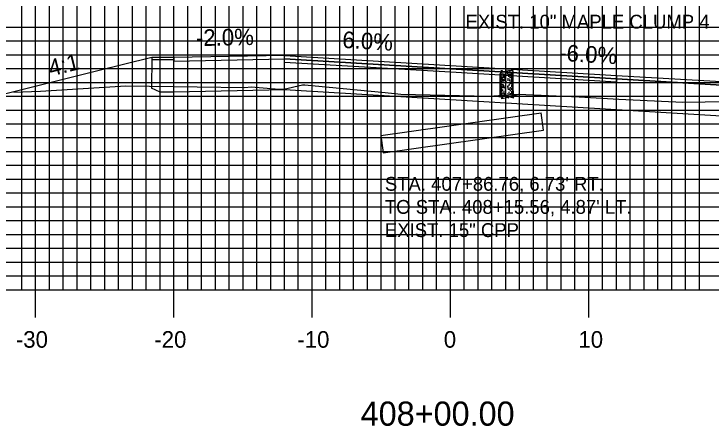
# Model space of a CAD drawing. Extents: x 852529 to 852872, y 364785 to 365005.
# Drawn here: x 852663.2 to 852713.6, y 364896.4 to 364926.2 of the extents above; entities that cross this region are included whole.
import ezdxf

# ---------------------------------------------------------------- set-up
doc = ezdxf.new("R2010")
doc.units = 0
for name, color, linetype in [('ANNOTATION', 7, 'Continuous'), ('D_Drainage_Culvert', 7, 'Continuous'), ('D_Roadway_Centerline', 7, 'Continuous'), ('D_Roadway_Edge_Shoulder', 7, 'Continuous'), ('D_Roadway_Edge_TW', 7, 'Continuous'), ('D_Roadway_Pavement', 7, 'Continuous'), ('D_Roadway_SubGrade', 7, 'Continuous'), ('D_Text_Monospaced', 7, 'Continuous'), ('H_V ANNOTATION', 7, 'Continuous'), ('MAJOR', 7, 'Continuous'), ('MINOR', 7, 'Continuous'), ('S_Roadway_Centerline', 7, 'Continuous'), ('S_Trees_Decid_NonPay', 7, 'Continuous')]:
    doc.layers.add(name, color=color, linetype=linetype)

msp = doc.modelspace()

# ---------------------------------------------------------------- linework, layer by layer
at = {"layer": 'ANNOTATION'}
for points in [[(852673.131, 364923.038), (852669.131, 364922.038), (852656.377, 364918.85)], [(852674.731, 364923.022), (852673.131, 364923.038), (852673.108, 364920.805)], [(852674.729, 364922.856), (852673.129, 364922.872)], [(852674.731, 364920.522), (852673.731, 364920.522), (852673.108, 364920.805)]]:
    msp.add_lwpolyline(points, dxfattribs=at)
at = {"layer": 'D_Drainage_Culvert'}
msp.add_line((852689.688, 364917.382), (852701.285, 364919.019), dxfattribs=at)
msp.add_lwpolyline([(852689.688, 364917.382), (852689.863, 364916.144), (852701.46, 364917.781), (852701.285, 364919.019)], dxfattribs=at)
at = {"layer": 'D_Roadway_Edge_Shoulder'}
for points in [[(852682.731, 364923.182), (852674.731, 364923.022), (852674.731, 364922.772), (852682.731, 364922.932)], [(852706.731, 364921.742), (852714.731, 364921.262), (852714.731, 364921.012), (852706.731, 364921.492)]]:
    msp.add_lwpolyline(points, close=True, dxfattribs=at)
at = {"layer": 'D_Roadway_Edge_TW'}
msp.add_lwpolyline([(852682.731, 364922.932), (852682.731, 364923.182), (852694.731, 364922.462), (852706.731, 364921.742), (852706.731, 364921.492), (852694.731, 364922.212)], close=True, dxfattribs=at)
at = {"layer": 'D_Roadway_Pavement'}
msp.add_lwpolyline([(852682.731, 364922.682), (852682.731, 364922.932), (852694.731, 364922.212), (852706.731, 364921.492), (852706.731, 364921.242), (852694.731, 364921.962)], close=True, dxfattribs=at)
at = {"layer": 'D_Roadway_SubGrade'}
msp.add_lwpolyline([(852682.731, 364920.682), (852674.731, 364920.522), (852674.731, 364922.772), (852674.731, 364923.022), (852674.731, 364922.772), (852682.731, 364922.932), (852694.731, 364922.212), (852706.731, 364921.492), (852714.731, 364921.012), (852714.731, 364921.262), (852727.889, 364917.973), (852706.731, 364919.242), (852694.731, 364919.962)], close=True, dxfattribs=at)
at = {"layer": 'MAJOR'}
for p, q in [((852664.731, 364906.233), (852664.731, 364936.233)), ((852674.731, 364906.233), (852674.731, 364936.233)), ((852684.731, 364906.233), (852684.731, 364936.233)), ((852694.731, 364906.233), (852694.731, 364936.233)), ((852704.731, 364906.233), (852704.731, 364936.233)), ((852554.731, 364921.233), (852834.731, 364921.233)), ((852554.731, 364916.233), (852834.731, 364916.233)), ((852554.731, 364911.233), (852834.731, 364911.233)), ((852554.731, 364906.233), (852834.731, 364906.233)), ((852554.731, 364906.233), (852834.731, 364906.233)), ((852664.731, 364904.229), (852664.731, 364906.233)), ((852674.731, 364904.229), (852674.731, 364906.233)), ((852684.731, 364904.229), (852684.731, 364906.233)), ((852694.731, 364904.229), (852694.731, 364906.233)), ((852704.731, 364904.229), (852704.731, 364906.233))]:
    msp.add_line(p, q, dxfattribs=at)
at = {"layer": 'MINOR'}
for p, q in [((852663.731, 364906.233), (852663.731, 364936.233)), ((852665.731, 364906.233), (852665.731, 364936.233)), ((852666.731, 364906.233), (852666.731, 364936.233)), ((852667.731, 364906.233), (852667.731, 364936.233)), ((852668.731, 364906.233), (852668.731, 364936.233)), ((852669.731, 364906.233), (852669.731, 364936.233)), ((852670.731, 364906.233), (852670.731, 364936.233)), ((852671.731, 364906.233), (852671.731, 364936.233)), ((852672.731, 364906.233), (852672.731, 364936.233)), ((852673.731, 364906.233), (852673.731, 364936.233)), ((852675.731, 364906.233), (852675.731, 364936.233)), ((852676.731, 364906.233), (852676.731, 364936.233)), ((852677.731, 364906.233), (852677.731, 364936.233)), ((852678.731, 364906.233), (852678.731, 364936.233)), ((852679.731, 364906.233), (852679.731, 364936.233)), ((852680.731, 364906.233), (852680.731, 364936.233)), ((852681.731, 364906.233), (852681.731, 364936.233)), ((852682.731, 364906.233), (852682.731, 364936.233)), ((852683.731, 364906.233), (852683.731, 364936.233)), ((852685.731, 364906.233), (852685.731, 364936.233)), ((852686.731, 364906.233), (852686.731, 364936.233)), ((852687.731, 364906.233), (852687.731, 364936.233)), ((852688.731, 364906.233), (852688.731, 364936.233)), ((852689.731, 364906.233), (852689.731, 364936.233)), ((852690.731, 364906.233), (852690.731, 364936.233)), ((852691.731, 364906.233), (852691.731, 364936.233)), ((852692.731, 364906.233), (852692.731, 364936.233)), ((852693.731, 364906.233), (852693.731, 364936.233)), ((852695.731, 364906.233), (852695.731, 364936.233)), ((852696.731, 364906.233), (852696.731, 364936.233)), ((852697.731, 364906.233), (852697.731, 364936.233)), ((852698.731, 364906.233), (852698.731, 364936.233)), ((852699.731, 364906.233), (852699.731, 364936.233)), ((852700.731, 364906.233), (852700.731, 364936.233)), ((852701.731, 364906.233), (852701.731, 364936.233)), ((852702.731, 364906.233), (852702.731, 364936.233)), ((852703.731, 364906.233), (852703.731, 364936.233)), ((852705.731, 364906.233), (852705.731, 364936.233)), ((852706.731, 364906.233), (852706.731, 364936.233)), ((852707.731, 364906.233), (852707.731, 364936.233)), ((852708.731, 364906.233), (852708.731, 364936.233)), ((852709.731, 364906.233), (852709.731, 364936.233)), ((852710.731, 364906.233), (852710.731, 364936.233)), ((852711.731, 364906.233), (852711.731, 364936.233)), ((852712.731, 364906.233), (852712.731, 364936.233)), ((852554.731, 364925.233), (852834.731, 364925.233)), ((852554.731, 364924.233), (852834.731, 364924.233)), ((852554.731, 364923.233), (852834.731, 364923.233)), ((852554.731, 364922.233), (852834.731, 364922.233)), ((852554.731, 364920.233), (852834.731, 364920.233)), ((852554.731, 364919.233), (852834.731, 364919.233)), ((852554.731, 364918.233), (852834.731, 364918.233)), ((852554.731, 364917.233), (852834.731, 364917.233)), ((852554.731, 364915.233), (852834.731, 364915.233)), ((852554.731, 364914.233), (852834.731, 364914.233)), ((852554.731, 364913.233), (852834.731, 364913.233)), ((852554.731, 364912.233), (852834.731, 364912.233)), ((852554.731, 364910.233), (852834.731, 364910.233)), ((852554.731, 364909.233), (852834.731, 364909.233)), ((852554.731, 364908.233), (852834.731, 364908.233)), ((852554.731, 364907.233), (852834.731, 364907.233))]:
    msp.add_line(p, q, dxfattribs=at)
at = {"layer": 'S_Roadway_Centerline'}
msp.add_lwpolyline([(852663.161, 364920.514), (852665.079, 364920.607), (852671.255, 364920.977), (852676.427, 364920.918), (852679.854, 364920.868), (852680.309, 364920.901), (852682.352, 364920.749), (852682.626, 364920.735), (852682.68, 364920.729), (852682.692, 364920.734), (852684.028, 364921.061), (852684.206, 364921.051), (852690.005, 364920.496), (852691.134, 364920.38), (852697.501, 364920.227), (852699.627, 364920.388), (852704.045, 364920.178), (852706.906, 364920.03), (852711.535, 364919.803), (852719.634, 364919.912)], dxfattribs=at)
at = {"layer": 'S_Trees_Decid_NonPay'}
for p, q in [((852698.351, 364921.742), (852698.351, 364921.66)), ((852698.378, 364921.812), (852698.378, 364921.595)), ((852698.421, 364921.807), (852698.421, 364921.755)), ((852698.421, 364921.652), (852698.421, 364921.57)), ((852698.578, 364921.818), (852698.578, 364921.739)), ((852698.578, 364921.652), (852698.578, 364921.568)), ((852698.876, 364921.87), (852698.876, 364921.763)), ((852699.023, 364921.916), (852699.023, 364921.768)), ((852699.023, 364921.72), (852699.023, 364921.551)), ((852699.141, 364921.899), (852699.141, 364921.598)), ((852699.21, 364921.986), (852699.21, 364921.891)), ((852699.21, 364921.665), (852699.21, 364921.582)), ((852698.351, 364921.591), (852698.351, 364921.461)), ((852698.351, 364921.438), (852698.351, 364921.257)), ((852698.351, 364921.209), (852698.351, 364920.963)), ((852698.378, 364921.526), (852698.378, 364921.374)), ((852698.378, 364921.269), (852698.378, 364921.191)), ((852698.378, 364921.164), (852698.378, 364921.057)), ((852698.421, 364921.535), (852698.421, 364921.461)), ((852698.421, 364921.434), (852698.421, 364921.374)), ((852698.421, 364921.321), (852698.421, 364921.14)), ((852698.492, 364921.634), (852698.492, 364921.547)), ((852698.492, 364921.477), (852698.492, 364921.356)), ((852698.492, 364921.28), (852698.492, 364921.166)), ((852698.578, 364921.457), (852698.578, 364921.356)), ((852698.578, 364921.271), (852698.578, 364921.195)), ((852698.696, 364921.634), (852698.696, 364921.434)), ((852698.876, 364921.535), (852698.876, 364921.448)), ((852698.876, 364921.413), (852698.876, 364921.343)), ((852699.023, 364921.245), (852699.023, 364921.096)), ((852699.141, 364921.57), (852699.141, 364921.438)), ((852699.141, 364921.404), (852699.141, 364921.123)), ((852699.21, 364921.512), (852699.21, 364921.261)), ((852699.21, 364921.178), (852699.21, 364920.948)), ((852698.349, 364920.796), (852698.351, 364920.536)), ((852698.351, 364920.944), (852698.351, 364920.849)), ((852698.378, 364921.022), (852698.378, 364920.921)), ((852698.378, 364920.896), (852698.378, 364920.713)), ((852698.421, 364921.108), (852698.421, 364921.026)), ((852698.421, 364920.972), (852698.421, 364920.802)), ((852698.421, 364920.768), (852698.421, 364920.489)), ((852698.492, 364921.104), (852698.492, 364921.022)), ((852698.492, 364920.936), (852698.492, 364920.839)), ((852698.492, 364920.709), (852698.492, 364920.61)), ((852698.578, 364921.01), (852698.578, 364920.913)), ((852698.696, 364920.896), (852698.696, 364920.709)), ((852698.696, 364920.678), (852698.696, 364920.625)), ((852698.876, 364921.01), (852698.876, 364920.787)), ((852699.023, 364920.827), (852699.023, 364920.674)), ((852699.141, 364921.053), (852699.141, 364920.909)), ((852699.141, 364920.839), (852699.141, 364920.697)), ((852699.21, 364920.878), (852699.21, 364920.717)), ((852699.21, 364920.701), (852699.21, 364920.596)), ((852698.298, 364920.25), (852698.366, 364920.281)), ((852698.38, 364920.371), (852698.345, 364920.32)), ((852698.351, 364920.497), (852698.351, 364920.423)), ((852698.378, 364920.61), (852698.378, 364920.419)), ((852698.421, 364920.436), (852698.421, 364920.411)), ((852698.492, 364920.481), (852698.492, 364920.423)), ((852698.578, 364920.588), (852698.578, 364920.364)), ((852698.696, 364920.449), (852698.696, 364920.359)), ((852698.836, 364920.168), (852698.87, 364920.314)), ((852698.876, 364920.454), (852698.876, 364920.388)), ((852699.023, 364920.462), (852699.023, 364920.384)), ((852699.141, 364920.596), (852699.141, 364920.415)), ((852699.142, 364920.355), (852699.183, 364920.259)), ((852699.21, 364920.559), (852699.21, 364920.435))]:
    msp.add_line(p, q, dxfattribs=at)
for points in [[(852698.31, 364921.85), (852698.31, 364920.438), (852698.288, 364920.289), (852698.084, 364920.246), (852698.224, 364920.211), (852698.443, 364920.192), (852698.512, 364920.149), (852698.391, 364920.06), (852698.722, 364920.104), (852698.836, 364920.168), (852698.928, 364920.108), (852698.984, 364920.186), (852698.975, 364920.223), (852699.037, 364920.225), (852699.089, 364920.168), (852699.321, 364920.116), (852699.194, 364920.205), (852699.326, 364920.207), (852699.634, 364920.244), (852699.395, 364920.275), (852699.317, 364920.333), (852699.278, 364920.454), (852699.261, 364920.808), (852699.261, 364922.041)], [(852698.405, 364921.93), (852698.409, 364922.025), (852698.423, 364921.998), (852698.423, 364922.119), (852698.444, 364922.056), (852698.459, 364922.089), (852698.475, 364922.033), (852698.492, 364922.05), (852698.51, 364922.041), (852698.529, 364921.974)], [(852698.427, 364921.806), (852698.444, 364921.868), (852698.467, 364921.856), (852698.498, 364921.891), (852698.531, 364921.813)], [(852698.897, 364921.875), (852698.906, 364921.942), (852698.93, 364921.947), (852698.939, 364921.982), (852698.969, 364921.967), (852698.984, 364921.982), (852699.008, 364921.959), (852699.031, 364921.967), (852699.044, 364922.016), (852699.051, 364921.973), (852699.082, 364921.982), (852699.086, 364921.93)], [(852698.349, 364920.297), (852698.428, 364920.281), (852698.444, 364920.238)], [(852698.428, 364920.281), (852698.471, 364920.316), (852698.479, 364920.364)], [(852698.576, 364920.316), (852698.57, 364920.246), (852698.506, 364920.234)], [(852698.687, 364920.31), (852698.687, 364920.273), (852698.636, 364920.242), (852698.619, 364920.192)], [(852699.212, 364920.392), (852699.221, 364920.316), (852699.299, 364920.266)]]:
    msp.add_lwpolyline(points, dxfattribs=at)
for centre, radius, start, end in [((852698.334, 364921.849), 0.0237, 161.8277, 175.7722), ((852698.328, 364921.85), 0.0179, 175.7722, 191.8277), ((852698.343, 364921.846), 0.0336, 143.0514, 161.8277), ((852698.328, 364921.85), 0.0179, 191.8277, 207.8832), ((852698.33, 364921.781), 0.0191, 173.8872, 180), ((852698.33, 364921.781), 0.0191, 180, 196.0515), ((852698.33, 364921.68), 0.0191, 173.8872, 180), ((852698.33, 364921.68), 0.0191, 180, 196.0515), ((852698.333, 364921.853), 0.0237, 207.8832, 221.8277), ((852698.336, 364921.782), 0.0252, 196.0515, 210), ((852698.336, 364921.682), 0.0252, 196.0515, 210), ((852698.345, 364921.788), 0.0356, 210, 228.7494), ((852698.345, 364921.687), 0.0356, 210, 228.7494), ((852698.341, 364921.859), 0.0336, 221.8277, 240.604), ((852698.391, 364921.81), 0.0935, 131.8277, 143.0514), ((852698.386, 364921.835), 0.0984, 228.7494, 240), ((852698.386, 364921.734), 0.0984, 228.7494, 240), ((852698.37, 364921.911), 0.0935, 240.604, 251.8277), ((852698.544, 364921.64), 0.322, 109.7098, 131.8277), ((852698.5, 364922.032), 0.326, 240, 248.0494), ((852698.5, 364921.931), 0.326, 240, 248.0494), ((852698.441, 364922.128), 0.322, 251.8277, 267.5521), ((852699.28, 364919.583), 2.507, 101.8277, 109.7098), ((852698.786, 364924.042), 2.356, 263.2266, 266.8519), ((852698.291, 364924.308), 2.507, 275.4987, 281.8277), ((852699.28, 364919.583), 2.507, 93.9457, 101.8277), ((852698.291, 364924.308), 2.507, 281.8277, 284.0013), ((852698.786, 364924.155), 2.356, 272.1614, 274.76), ((852698.786, 364924.042), 2.356, 272.6327, 275.758), ((852698.786, 364924.155), 2.356, 276.7201, 278.1032), ((852698.291, 364924.308), 2.507, 288.4719, 289.7098), ((852699.13, 364921.763), 0.322, 71.8277, 93.9457), ((852699.073, 364922.145), 0.326, 278.1032, 282.1964), ((852699.028, 364922.251), 0.322, 289.7098, 311.8277), ((852699.073, 364922.032), 0.326, 282.1964, 299.0901), ((852699.073, 364922.145), 0.326, 291.6757, 300), ((852699.073, 364921.931), 0.326, 296.4281, 300), ((852699.201, 364921.98), 0.0935, 60.604, 71.8277), ((852699.186, 364921.948), 0.0984, 300, 311.2506), ((852699.186, 364921.734), 0.0984, 300, 311.2506), ((852699.18, 364922.081), 0.0935, 311.8277, 323.0514), ((852699.231, 364922.032), 0.0336, 41.8277, 60.604), ((852699.228, 364921.901), 0.0356, 311.2506, 330), ((852699.228, 364921.687), 0.0356, 311.2506, 330), ((852699.228, 364922.045), 0.0336, 323.0514, 341.8277), ((852699.238, 364922.039), 0.0237, 27.8832, 41.8277), ((852699.243, 364922.041), 0.0179, 11.8277, 27.8832), ((852699.237, 364921.896), 0.0252, 330, 343.9485), ((852699.237, 364921.682), 0.0252, 330, 343.9485), ((852699.237, 364922.042), 0.0237, 341.8277, 355.7722), ((852699.243, 364922.041), 0.0179, 355.7722, 11.8277), ((852699.243, 364921.894), 0.0191, 0, 16.0515), ((852699.243, 364921.894), 0.0191, 343.9485, 0), ((852699.243, 364921.68), 0.0191, 0, 16.0515), ((852699.243, 364921.68), 0.0191, 343.9485, 0), ((852698.329, 364921.242), 0.0191, 173.8872, 180), ((852698.329, 364921.242), 0.0191, 180, 196.0515), ((852698.33, 364921.577), 0.0191, 173.8872, 180), ((852698.33, 364921.577), 0.0191, 180, 196.0515), ((852698.33, 364921.472), 0.0191, 173.8872, 180), ((852698.33, 364921.472), 0.0191, 180, 196.0515), ((852698.33, 364921.357), 0.0191, 173.8872, 180), ((852698.33, 364921.357), 0.0191, 180, 196.0515), ((852698.335, 364921.244), 0.0252, 196.0515, 210), ((852698.336, 364921.474), 0.0252, 196.0515, 210), ((852698.336, 364921.359), 0.0252, 196.0515, 210), ((852698.344, 364921.249), 0.0356, 210, 228.7494), ((852698.332, 364921.142), 0.0191, 173.8872, 180), ((852698.345, 364921.479), 0.0356, 210, 228.7494), ((852698.345, 364921.364), 0.0356, 210, 228.7494), ((852698.386, 364921.297), 0.0984, 228.7494, 240), ((852698.386, 364921.526), 0.0984, 228.7494, 240), ((852698.386, 364921.411), 0.0984, 228.7494, 240), ((852698.5, 364921.494), 0.326, 240, 242.9942), ((852698.5, 364921.723), 0.326, 240, 248.0494), ((852698.5, 364921.608), 0.326, 240, 255.9618), ((852698.5, 364921.494), 0.326, 248.1902, 256.0964), ((852698.5, 364921.828), 0.326, 255.9618, 261.8968), ((852698.5, 364921.723), 0.326, 255.9618, 261.8968), ((852698.5, 364921.931), 0.326, 260.9146, 261.8968), ((852698.786, 364923.941), 2.356, 261.8968, 264.9353), ((852698.786, 364923.838), 2.356, 261.8968, 262.6162), ((852698.786, 364923.733), 2.356, 261.8968, 262.8132), ((852698.786, 364923.618), 2.356, 262.8132, 264.9353), ((852698.786, 364923.733), 2.356, 264.9353, 266.9933), ((852698.786, 364923.838), 2.356, 266.0259, 267.8019), ((852698.786, 364923.618), 2.356, 267.586, 270), ((852698.786, 364923.941), 2.356, 267.8019, 269.1881), ((852698.786, 364923.618), 2.356, 270, 270.4422), ((852698.786, 364923.838), 2.356, 272.1614, 273.4964), ((852698.786, 364923.733), 2.356, 274.3638, 276.7318), ((852698.786, 364923.838), 2.356, 275.0054, 276.6587), ((852698.786, 364923.618), 2.356, 275.2089, 277.3412), ((852698.786, 364923.504), 2.356, 277.1385, 278.1032), ((852698.786, 364923.941), 2.356, 277.4481, 278.1032), ((852699.072, 364921.494), 0.326, 278.1032, 282.3301), ((852699.073, 364921.931), 0.326, 278.1032, 289.5833), ((852699.073, 364921.828), 0.326, 282.1964, 288.3169), ((852699.073, 364921.723), 0.326, 282.1964, 294.8455), ((852699.072, 364921.494), 0.326, 292.1344, 300), ((852699.073, 364921.608), 0.326, 294.8455, 300), ((852699.073, 364921.828), 0.326, 296.757, 300), ((852699.186, 364921.297), 0.0984, 300, 311.2506), ((852699.186, 364921.631), 0.0984, 300, 311.2506), ((852699.186, 364921.411), 0.0984, 300, 311.2506), ((852699.228, 364921.584), 0.0356, 311.2506, 330), ((852699.228, 364921.364), 0.0356, 311.2506, 330), ((852699.227, 364921.249), 0.0356, 311.2506, 330), ((852699.236, 364921.244), 0.0252, 330, 343.9485), ((852699.237, 364921.579), 0.0252, 330, 343.9485), ((852699.237, 364921.359), 0.0252, 330, 343.9485), ((852699.242, 364921.242), 0.0191, 0, 16.0515), ((852699.242, 364921.242), 0.0191, 343.9485, 0), ((852699.243, 364921.577), 0.0191, 0, 16.0515), ((852699.243, 364921.577), 0.0191, 343.9485, 0), ((852699.243, 364921.357), 0.0191, 0, 16.0515), ((852699.243, 364921.357), 0.0191, 343.9485, 0), ((852699.245, 364921.142), 0.0191, 0, 16.0515), ((852698.33, 364921.037), 0.0191, 173.8872, 180), ((852698.33, 364921.037), 0.0191, 180, 196.0515), ((852698.33, 364920.947), 0.0191, 173.8872, 180), ((852698.336, 364921.039), 0.0252, 196.0515, 210), ((852698.332, 364921.142), 0.0191, 180, 196.0515), ((852698.338, 364921.144), 0.0252, 196.0515, 210), ((852698.345, 364921.044), 0.0356, 210, 228.7494), ((852698.334, 364920.718), 0.0191, 173.8872, 180), ((852698.334, 364920.718), 0.0191, 180, 196.0515), ((852698.34, 364920.72), 0.0252, 196.0515, 210), ((852698.347, 364921.149), 0.0356, 210, 228.7494), ((852698.349, 364920.725), 0.0356, 210, 228.7494), ((852698.386, 364921.092), 0.0984, 228.7494, 240), ((852698.389, 364921.196), 0.0984, 228.7494, 240), ((852698.39, 364920.773), 0.0984, 228.7494, 240), ((852698.5, 364921.289), 0.326, 240, 242.8475), ((852698.503, 364921.394), 0.326, 240, 247.5951), ((852698.5, 364921.289), 0.326, 248.0494, 255.9618), ((852698.5, 364921.085), 0.326, 248.0494, 255.9618), ((852698.504, 364920.97), 0.326, 255.2259, 261.8968), ((852698.791, 364922.98), 2.356, 261.8968, 262.7137), ((852698.789, 364923.404), 2.356, 262.7545, 265.0266), ((852698.786, 364923.299), 2.356, 263.572, 264.9353), ((852698.786, 364923.208), 2.356, 264.7274, 267.8019), ((852698.786, 364923.299), 2.356, 270.9946, 272.1614), ((852698.786, 364923.095), 2.356, 272.531, 275.758), ((852698.789, 364923.404), 2.356, 273.1471, 275.6557), ((852698.786, 364923.208), 2.356, 275.5135, 277.4157), ((852698.791, 364922.98), 2.356, 275.5148, 277.7774), ((852699.075, 364921.394), 0.326, 283.0921, 300), ((852699.073, 364921.198), 0.326, 286.0817, 298.061), ((852699.073, 364921.289), 0.326, 294.8455, 300), ((852699.077, 364920.97), 0.326, 294.0625, 300), ((852699.186, 364921.092), 0.0984, 300, 311.2506), ((852699.191, 364920.773), 0.0984, 300, 311.2506), ((852699.228, 364921.044), 0.0356, 311.2506, 330), ((852699.232, 364920.725), 0.0356, 311.2506, 330), ((852699.237, 364921.039), 0.0252, 330, 343.9485), ((852699.243, 364921.037), 0.0191, 0, 16.0515), ((852699.243, 364921.037), 0.0191, 343.9485, 0), ((852699.241, 364920.72), 0.0252, 330, 343.9485), ((852699.247, 364920.718), 0.0191, 0, 16.0515), ((852699.247, 364920.718), 0.0191, 343.9485, 0), ((852698.345, 364920.498), 0.0191, 173.8872, 180), ((852698.345, 364920.498), 0.0191, 180, 196.0515), ((852698.35, 364920.499), 0.0252, 196.0515, 210), ((852698.359, 364920.504), 0.0356, 210, 228.7494), ((852698.401, 364920.552), 0.0984, 228.7494, 240), ((852698.509, 364920.859), 0.326, 240, 246.3456), ((852698.515, 364920.749), 0.326, 245.2906, 261.8968), ((852698.801, 364922.759), 2.356, 261.8968, 262.4597), ((852698.795, 364922.869), 2.356, 264.7171, 265.8136), ((852698.801, 364922.759), 2.356, 264.5833, 265.4449), ((852698.795, 364922.869), 2.356, 273.1842, 275.0911), ((852698.801, 364922.759), 2.356, 276.4667, 278.1032), ((852699.087, 364920.749), 0.326, 278.1032, 279.6166), ((852699.087, 364920.749), 0.326, 292.0839, 300), ((852699.082, 364920.859), 0.326, 298.0903, 300), ((852699.195, 364920.662), 0.0984, 300, 311.2506), ((852699.201, 364920.552), 0.0984, 300, 311.2506), ((852699.237, 364920.615), 0.0356, 311.2506, 330), ((852699.242, 364920.504), 0.0356, 311.2506, 330), ((852699.246, 364920.61), 0.0252, 330, 343.9485), ((852699.252, 364920.608), 0.0191, 0, 16.0515), ((852699.252, 364920.608), 0.0191, 343.9485, 0), ((852699.251, 364920.499), 0.0252, 330, 343.9485), ((852699.257, 364920.498), 0.0191, 0, 16.0515), ((852699.257, 364920.498), 0.0191, 343.9485, 0)]:
    msp.add_arc(centre, radius, start, end, dxfattribs=at)

# ---------------------------------------------------------------- texts
at = {"layer": 'ANNOTATION'}
for s, rotation, p in [('-2.0%', 1.1458, (852676.337, 364923.855)), ('6.0%', 356.5664, (852686.885, 364923.737)), ('-6.0%', 356.5664, (852702.565, 364922.796)), ('4:1', 14.0362, (852665.832, 364921.659))]:
    msp.add_text(s, height=1.2, rotation=rotation, dxfattribs=at).set_placement(p)
at = {"layer": 'D_Roadway_Centerline'}
for s, p in [('C', (852694.725, 364922.462)), ('L', (852694.731, 364922.455))]:
    msp.add_text(s, height=0.0146, dxfattribs=at).set_placement(p)
at = {"layer": 'D_Text_Monospaced'}
for s, p in [('EXIST. 10" MAPLE CLUMP 4', (852695.823, 364925.124)), ("STA. 407+86.76, 6.73' RT.", (852689.99, 364913.391)), ("TO STA. 408+15.56, 4.87' LT.", (852689.99, 364911.723)), ('EXIST. 15" CPP', (852689.99, 364910.043))]:
    msp.add_text(s, height=0.99996, dxfattribs=at).set_placement(p)
at = {"layer": 'H_V ANNOTATION'}
for s, height, p in [('-30', 1.2, (852663.307, 364902.033)), ('-20', 1.2, (852673.318, 364902.033)), ('-10', 1.2, (852683.66, 364902.033)), ('0', 1.2, (852694.249, 364902.033)), ('10', 1.2, (852703.981, 364902.033)), ('408+00.00', 1.75, (852688.238, 364896.389))]:
    msp.add_text(s, height=height, dxfattribs=at).set_placement(p)

doc.saveas('drawing.dxf')
